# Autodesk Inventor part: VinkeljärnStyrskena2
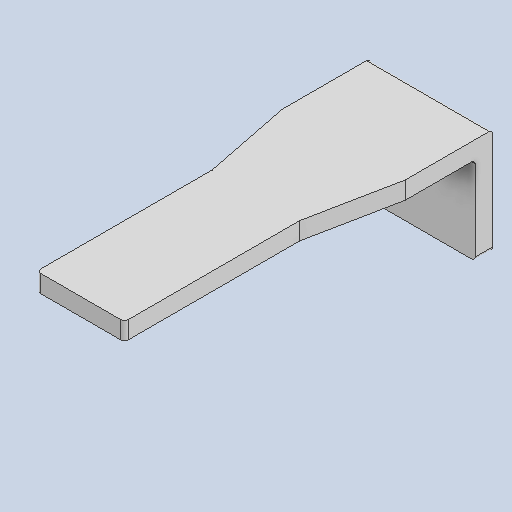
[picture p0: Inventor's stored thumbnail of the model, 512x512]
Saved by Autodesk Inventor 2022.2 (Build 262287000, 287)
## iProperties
Created: 2019-07
Part Number: VinkeljärnStyrskena2
Material: Generic
Document SubType Name: Modeling
Designer: cl
Density: 1 g/cm^3
Appearance: Default
Author: cl
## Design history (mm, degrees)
sketch "Sketch1"
  geometry: L1 (0, 0)-(70, 0); L2 (70, 0)-(70, 60); L3 (70, 60)-(0, 60); L4 (0, 60)-(0, 0)
  constraints: 8 end point, 2 parallel, 1 horizontal, 1 perpendicular
  dimensions: "d0" = 70 distance of L3.end L2.end; "d1" = 60 distance of L2.end L1.end
extrude "Extrusion1" new body sketch "Sketch1" distance "d2" = 10; taper "d3" = 0 deg
sketch "Sketch3"
  geometry: L1 (0, 0)-(70, 0) reference; L2 (0, 0)-(0, -50); L3 (0, -50)-(10, -100); L4 (10, -100)-(10, -200); L5 (10, -200)-(60, -200); L6 (60, -200)-(60, -100); L7 (60, -100)-(70, -50); L8 (70, -50)-(70, 0)
  constraints: 14 end point, 2 parallel, 2 perpendicular, 1 vertical
  dimensions: "d4" = 50 distance of L1.start L2.end; "d5" = 50 distance between parallel lines of L6 L4; "d6" = 200 distance between parallel lines of L1 L5; "d7" = 100 distance of L3.end L4.end; "d8" = 10 distance between parallel lines of L2 L4; "d9" = 50 distance of L7.end L1.end; "d10" = 100 distance of L5.end L6.end
extrude "Extrusion2" join sketch "Sketch3" distance "d11" = 10; taper "d12" = 0 deg
fillet "Fillet1" dims "d13" = 2
body "Solid1"
